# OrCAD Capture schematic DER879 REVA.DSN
size Custom
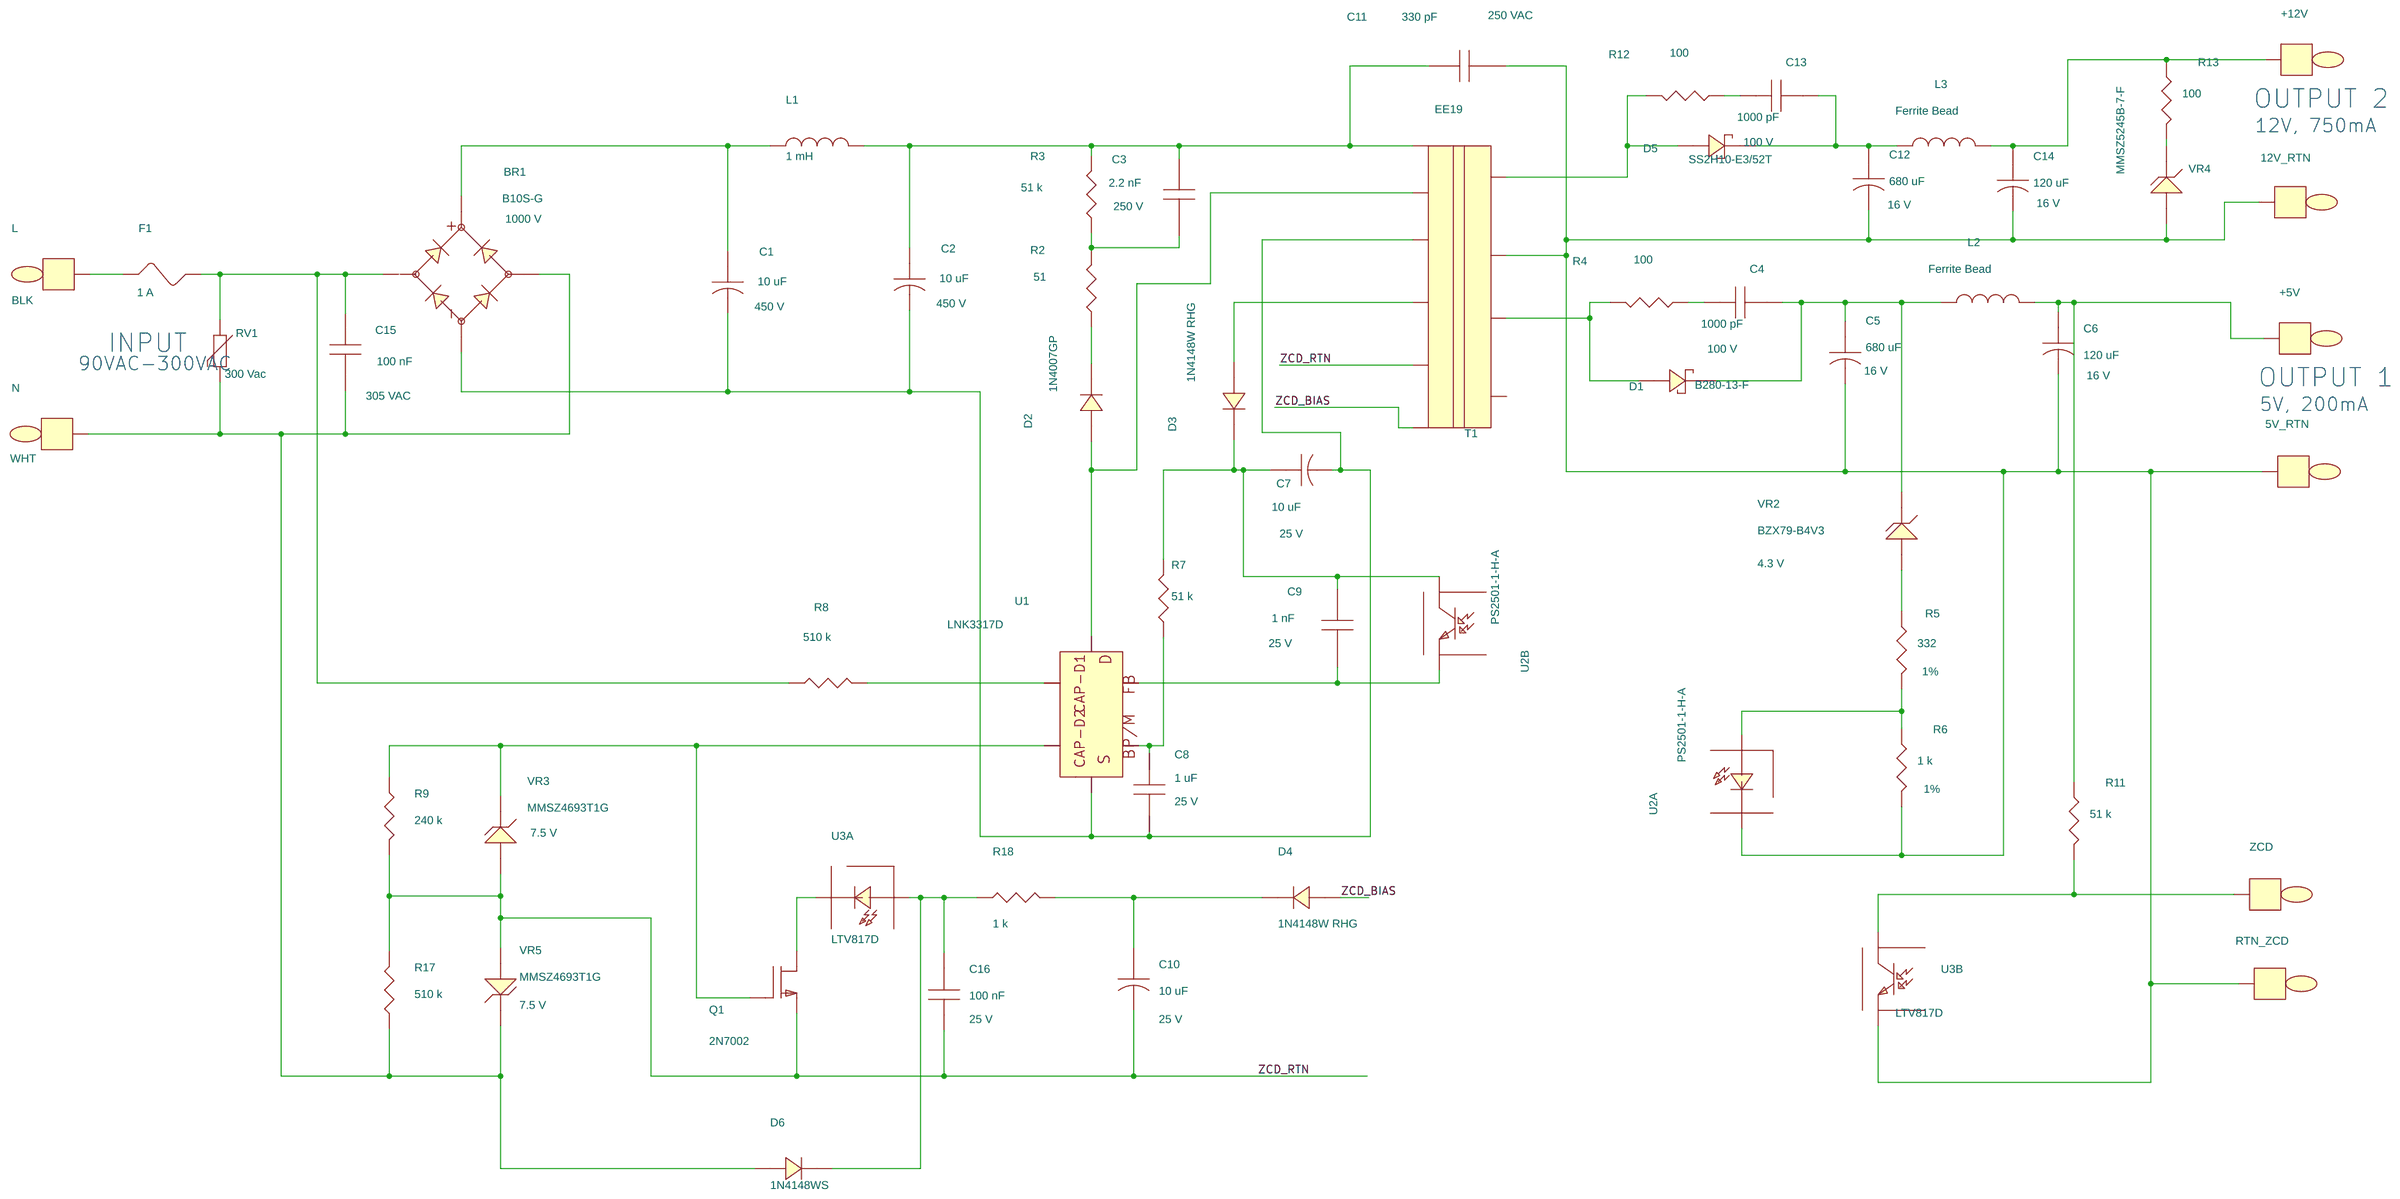
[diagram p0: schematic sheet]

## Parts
5V_RTN  BLK  [pitpkeystone100x100]
12V_RTN  BLK  [pitpkeystone100x100]
+5V  RED  [pitpkeystone100x100]
+12V  RED  [pitpkeystone100x100]
BR1  B10S-G  [pismsoic4]
C1  10 uF  [pipolcapclyd500ls200040]
C2  10 uF  [pipolcapclyd500ls200040]
C3  2.2 nF  [pismc0805]
C4  1000 pF  [pismc0603]
C5  680 uF  [pipolcapcyld400ls200040]
C6  120 uF  [pipolcapcyld250ls100030]
C7  10 uF  [pipolcapclyd200ls80030]
C8  1 uF  [pismc0805]
C9  1 nF  [pismc0603]
C10  10 uF  [pipolcapclyd200ls80030]
C11  330 pF  [pinpcaprad394x275394030]
C12  680 uF  [pipolcapcyld400ls200040]
C13  1000 pF  [pismc0603]
C14  120 uF  [pipolcapcyld250ls100030]
C15  100 nF  [pinpxcaprad475x255395040]
C16  100 nF  [pismc0603]
D1  B280-13-F  [pismsmb]
D2  1N4007GP  [pidv200x110x040do41]
D3  1N4148W RHG  [pi_sm_sod-123_12]
D4  1N4148W RHG  [pi_sm_sod-123_12]
D5  SS2H10-E3/52T  [pismsmb]
D6  1N4148WS  [pismdsod323]
F1  1 A  [pi_rst_microfuse]
L  BLK  [pitpkeystone125x125]
L1  1 mH  [pichoke030dials200035]
L2  Ferrite Bead  [pi12wresd180ls675d040]
L3  Ferrite Bead  [pi12wresd180ls675d040]
N  WHT  [pitpkeystone125x125]
Q1  2N7002  [pismsot23123_1]
R2  51  [pismr1206]
R3  51 k  [pismr1206]
R4  100  [pismr1206]
R5  332  [pismr0603]
R6  1 k  [pismr0603]
R7  51 k  [pismr0805]
R8  510 k  [pismr1206]
R9  240 k  [pismr1206]
R11  51 k  [pismr0603]
R12  100  [pismr1206]
R13  100  [pismr0805]
R17  510 k  [pismr0805]
R18  1 k  [pismr0603]
RTN_ZCD  BLK  [pitpkeystone100x100]
RV1  300 Vac  [pidisc350x225ls240x140040]
T1  EE19  [pi_bobbin_ee19_10p]
U1  LNK3317D  [pismso8_nop3]
U2  PS2501-1-H-A  [pi_dip4]  (sections A,B)
U3  LTV817D  [pi_dip4]  (sections A,B)
VR2  BZX79-B4V3  [pidv200x080x030do35]
VR3  MMSZ4693T1G  [pi_sm_sod-123_12]
VR4  MMSZ5245B-7-F  [pi_sm_sod-123_12]
VR5  MMSZ4693T1G  [pi_sm_sod-123_12]
ZCD  BLUE  [pitpkeystone100x100]

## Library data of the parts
5V_RTN 12V_RTN RTN_ZCD = TESTPOINT: Part Number: 35-00079-00
+5V +12V = TESTPOINT: Part Number: 35-00080-00
BR1 = DIODE_BRIDGE_~~+-: ALT_SYMBOLS: pi_sm_soic4_slot; Disp_Voltage: 1000 V; FPLIST: pismsoic4,pi_sm_soic4_slot; Part Number: 15-00818-00
C1 C2 = CAP_POL: ALT_SYMBOLS: pipolcapclyd500ls200040800lh; Disp_Voltage: 450 V; FPLIST: pipolcapclyd500ls200040,pipolcapclyd500ls200040800lh; Part Number: 20-00684-00; Voltage: 450 V
C3 = CAP_NP: Disp_Voltage: 250 V; Part Number: 20-08766-00; Voltage: 250 V
C4 C13 = CAP_NP: Disp_Voltage: 100 V; Part Number: 20-00712-00; Voltage: 100 V
C5 C12 = CAP_POL: ALT_SYMBOLS: pipolcapclyd395x630ls200030h; Disp_Voltage: 16 V; FPLIST: pipolcapcyld400ls200040,pipolcapclyd395x630ls200030h; Part Number: 20-00018-00; Voltage: 16 V
C6 C14 = CAP_POL: ALT_SYMBOLS: pipolcapcyld250ls100030h; Disp_Voltage: 16 V; FPLIST: pipolcapcyld250ls100030,pipolcapcyld250ls100030h; Part Number: 20-00784-00; Voltage: 16 V
C7 C10 = CAP_POL: ALT_SYMBOLS: pipolcapclyd200ls80030h; Disp_Voltage: 25 V; FPLIST: pipolcapclyd200ls80030,pipolcapclyd200ls80030h; Part Number: 20-01182-00; Voltage: 25 V
C8 = CAP_NP: Disp_Voltage: 25 V; Part Number: 20-09171-00; Voltage: 25 V
C9 = CAP_NP: Disp_Voltage: 25 V; Part Number: 20-08948-00; Voltage: 25 V
C11 = CAP_NP: Disp_Voltage: 250 VAC; Part Number: 20-00743-00; Voltage: 250 VAC
C15 = CAP_NP: ALT_SYMBOLS: pinpxcaprad475x255395040_h; Disp_Voltage: 305 VAC; FPLIST: pinpxcaprad475x255395040,pinpxcaprad475x255395040_h; Part Number: 20-01047-00; Voltage: 305 VAC
C16 = CAP_NP: Disp_Voltage: 25 V; Part Number: 20-01050-00; Voltage: 25 V
D1 = DIODE_SCHOTTKY: Part Number: 15-01294-00
D2 = DIODE: ALT_SYMBOLS: pidax475x125040do41,pidv200x110x040do41wbead,pidax390x125040do41; FPLIST: pidv200x110x040do41,pidax475x125040do41,pidv200x110x040do41wbead,pidax390x125040do41; Part Number: 15-00293-00
D3 D4 = DIODE: ALT_SYMBOLS: pi_sm_sod-123_12_1; FPLIST: pi_sm_sod-123_12,pi_sm_sod-123_12_1; Part Number: 15-01269-00
D5 = DIODE_SCHOTTKY: Disp_Voltage: 100 V; Part Number: 15-00995-00
D6 = DIODE: Part Number: 15-01163-00
F1 = FUSE: ALT_SYMBOLS: pirstmicrofusehoz; FPLIST: pi_rst_microfuse,pirstmicrofusehoz; Part Number: 40-00053-00
L = TESTPOINT: Part Number: 35-00042-00
L1 = INDUCTOR: Part Number: 30-00165-00
L2 L3 = INDUCTOR: ALT_SYMBOLS: pi12wvresd180ls150d040,pi12wvresd180ls200d040,pi12wvresd180ls250d040; FPLIST: pi12wresd180ls675d040,pi12wvresd180ls150d040,pi12wvresd180ls200d040,pi12wvresd180ls250d040; Part Number: 30-00143-00
N = TESTPOINT: Part Number: 35-00044-00
Q1 = FET_N_GSD: Part Number: 50-00103-00
R2 = R: Part Number: 05-01321-00
R3 = R: Part Number: 05-01393-00
R4 R12 = R: Part Number: 05-01328-00
R5 = R: Disp_Tol: 1%; Part Number: 05-01032-00
R6 = R: Disp_Tol: 1%; Part Number: 05-01078-00
R7 = R: Part Number: 05-01560-00
R8 = R: Part Number: 05-01417-00
R9 = R: Part Number: 05-01409-00
R11 = R: Part Number: 05-01729-00
R13 = R: Part Number: 05-01495-00
R17 = R: Part Number: 05-01584-00
R18 = R: Part Number: 05-01688-00
RV1 = VARISTOR: Part Number: 85-00031-00
T1 = BEE19_10P_TF1939: Part Number: 25-00924-00
U1 = LNK-TNZ: Part Number: 10-01309-00
U2 = OPTO_A_B: Part Number: 53-00010-00
U3 = OPTO_A_B: Part Number: 53-00019-00
VR2 = DIODE_ZENER: ALT_SYMBOLS: pidax375x070030do35; Disp_Voltage: 4.3 V; FPLIST: pidv200x080x030do35,pidax375x070030do35; Part Number: 15-00222-00
VR3 VR5 = DIODE_ZENER: Disp_Voltage: 7.5 V; Part Number: 15-01578-00
VR4 = DIODE_ZENER: Part Number: 15-01091-00
ZCD = TESTPOINT: Part Number: 35-00397-00

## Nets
ZCD_BIAS: D4.2 T1.6
ZCD_RTN: C10.2 C16.1 Q1.2(S) R9.1 R17.2 T1.5 VR3.2 VR5.2
N4253666: C4.1 R4.1
N4253670: C4.2 C5.1 D1.1 L2.1 VR2.1
N4254079: BR1.4 C1.2 C2.2 C7.2 C8.2 T1.3 U1.5
N4254091: C7.1 C9.1 D3.1 R7.2 U2.4(C)
N4254098: C2.1 C3.1 C11.1 L1.2 R3.1 T1.1
N4254129: C3.2 R2.1 R3.2
N4254146: D2.1 R2.2
N4254163: D2.2 T1.2 U1.4
N4254354: C8.1 R7.1 U1.7
N4254668: C9.2 U1.8 U2.3(E)
N4254798: R5.1 VR2.2
N4254829: R5.2 R6.1 U2.1(A)
N4254835: 5V_RTN.1 12V_RTN.1 C5.2 C6.2 C11.2 C12.2 C14.2 R6.2 RTN_ZCD.1 T1.9 U2.2(C) U3.3(E) VR4.2
N4255085: BR1.3 C1.1 L1.1
N4255357: BR1.2 C15.1 F1.2 R8.1 RV1.1
N4255405: BR1.1 C15.2 D6.2 N.1 R17.1 RV1.2 VR5.1
N4255537: R8.2 U1.1
N4259135: Q1.1(G) R9.2 U1.2 VR3.1
N4259699: R11.2 U3.4(C) ZCD.1
N4286558: Q1.3(D) U3.2(C)
N4286955: C10.1 D4.1 R18.2
N4288983: D1.2 R4.2 T1.8
N4289137: C13.1 R12.1
N4289155: D5.2 R12.2 T1.10
N4289170: C12.1 C13.2 D5.1 L3.1
N4289478: +5V.1 C6.1 L2.2 R11.1
N4289689: +12V.1 C14.1 L3.2 R13.1
N4291278: R13.2 VR4.1
N4297184: D3.2 T1.4
N4320314: C16.2 D6.1 R18.1 U3.1(A)
N4330584: F1.1 L.1

Not connected (* = marked no-connect by the designer): T1 7; U1 6

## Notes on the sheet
- OUTPUT 2
- 12V, 750mA
- INPUT
- 90VAC-300VAC
- OUTPUT 1
- 5V, 200mA
